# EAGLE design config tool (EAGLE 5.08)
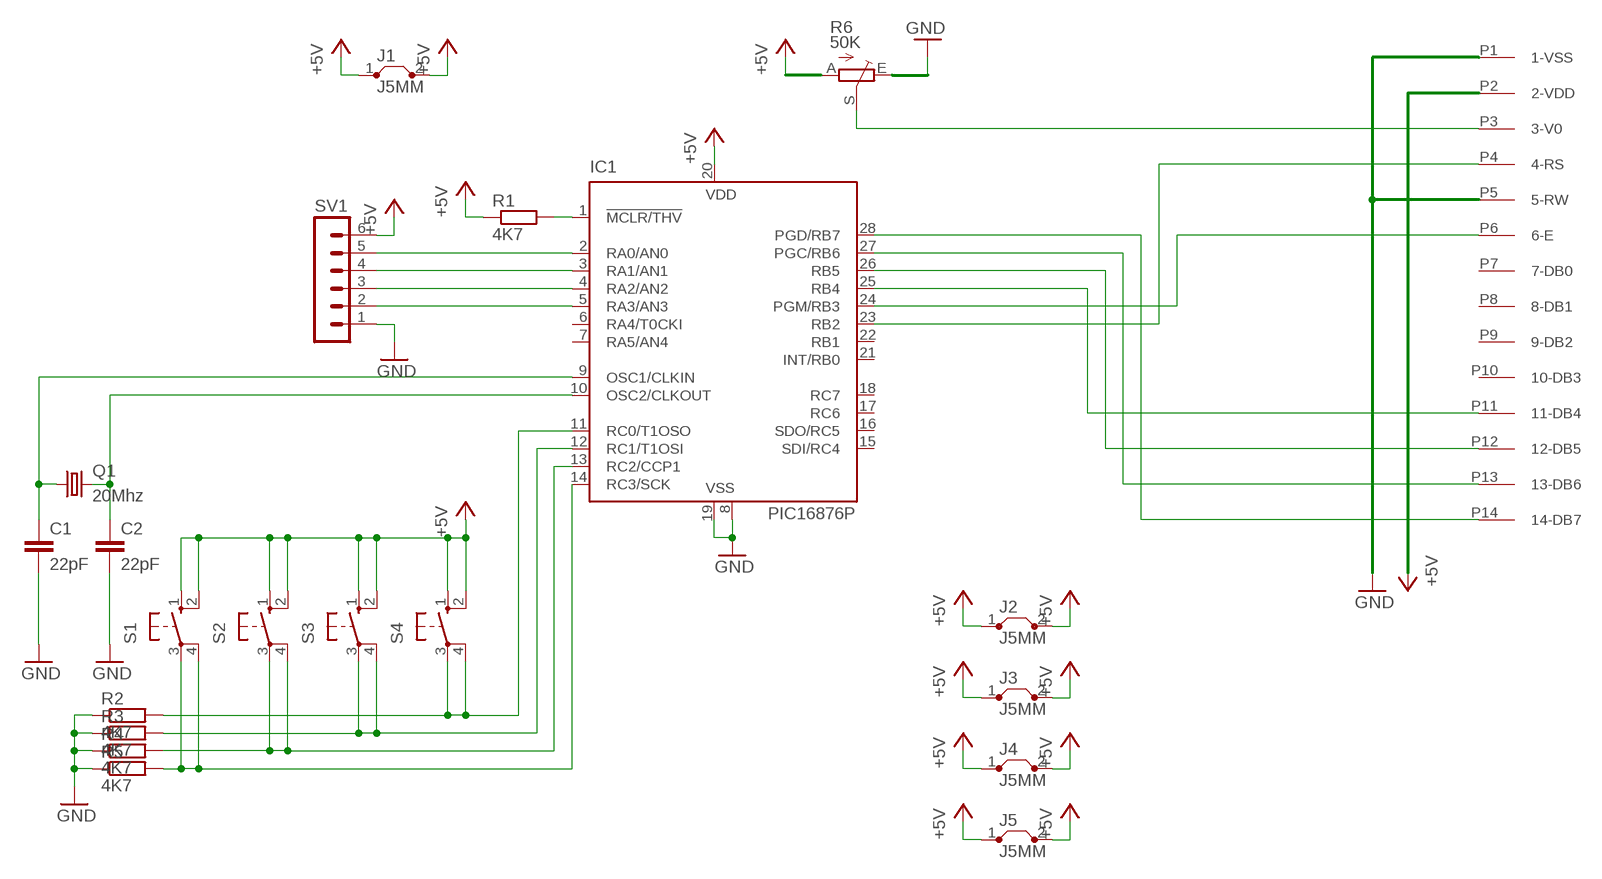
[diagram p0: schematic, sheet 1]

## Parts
C1  22pF  C-EU025-025X050  [C025-025X050]
C2  22pF  C-EU025-025X050  [C025-025X050]
IC1  PIC16876P  [DIL28-3]
J1  J5MM  [05]
J2  J5MM  [05]
J3  J5MM  [05]
J4  J5MM  [05]
J5  J5MM  [05]
Q1  20Mhz  CRYSTALHC18U-V  [HC18U-V]
R1  4K7  R-EU_0207/7  [0207/7]
R2  4K7  R-EU_0207/12  [0207/12]
R3  4K7  R-EU_0207/12  [0207/12]
R4  4K7  R-EU_0207/12  [0207/12]
R5  4K7  R-EU_0207/12  [0207/12]
R6  50K  TRIM_EU-B25P  [B25P]
S1  10-XX  [B3F-10XX]
S2  10-XX  [B3F-10XX]
S3  10-XX  [B3F-10XX]
S4  10-XX  [B3F-10XX]
SV1  MA06-1  [MA06-1]
U$1  16X2LCD  [NO_BACKLIGHT]

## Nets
+5V: IC1.20(VDD) J1.1 J1.2 J2.1 J2.2 J3.1 J3.2 J4.1 J4.2 J5.1 J5.2 R1.1 R6.A S1.1(S) S1.2(S1) S2.1(S) S2.2(S1) S3.1(S) S3.2(S1) S4.1(S) S4.2(S1) SV1.6 U$1.P2(2-VDD)
GND: C1.2 C2.2 IC1.8(VSS) IC1.19(VSS) R2.1 R3.1 R4.1 R5.1 R6.E SV1.1 U$1.P1(1-VSS) U$1.P5(5-RW)
N$1: IC1.28(PGD/RB7) U$1.P14(14-DB7)
N$2: IC1.27(PGC/RB6) U$1.P13(13-DB6)
N$3: IC1.26(RB5) U$1.P12(12-DB5)
N$4: IC1.25(RB4) U$1.P11(11-DB4)
N$5: IC1.23(RB2) U$1.P4(4-RS)
N$6: IC1.24(PGM/RB3) U$1.P6(6-E)
N$7: R6.S U$1.P3(3-V0)
N$8: C2.1 IC1.10(OSC2/CLKOUT) Q1.2
N$9: IC1.2(RA0/AN0) SV1.5
N$10: IC1.3(RA1/AN1) SV1.4
N$11: IC1.4(RA2/AN2) SV1.3
N$12: IC1.5(RA3/AN3) SV1.2
N$13: C1.1 IC1.9(OSC1/CLKIN) Q1.1
N$14: IC1.1(!MCLR/THV) R1.2
N$15: IC1.11(RC0/T1OSO) R2.2 S4.3(P) S4.4(P1)
N$16: IC1.12(RC1/T1OSI) R3.2 S3.3(P) S3.4(P1)
N$17: IC1.13(RC2/CCP1) R4.2 S2.3(P) S2.4(P1)
N$18: IC1.14(RC3/SCK) R5.2 S1.3(P) S1.4(P1)
Unconnected: IC1.6(RA4/T0CKI) IC1.7(RA5/AN4) IC1.15(SDI/RC4) IC1.16(SDO/RC5) IC1.17(RC6) IC1.18(RC7) IC1.21(INT/RB0) IC1.22(RB1) U$1.P7(7-DB0) U$1.P8(8-DB1) U$1.P9(9-DB2) U$1.P10(10-DB3)

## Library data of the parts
C1 C2 = rcl:C-EU: CAPACITOR, European symbol
IC1 = microchip:PIC16*876: MICROCONTROLLER flash type
J1-J5 = jumper:J: Bridge
Q1 = crystal:CRYSTAL: CRYSTAL
R1-R5 = rcl:R-EU_: RESISTOR, European symbol
R6 = pot:TRIM_EU-: POTENTIOMETER
S1-S4 = switch-omron:10-XX: OMRON SWITCH
SV1 = con-lstb:MA06-1: PIN HEADER
U$1 = lcd_nobacklight:16X2LCD: 16x2 LCD - no backlight

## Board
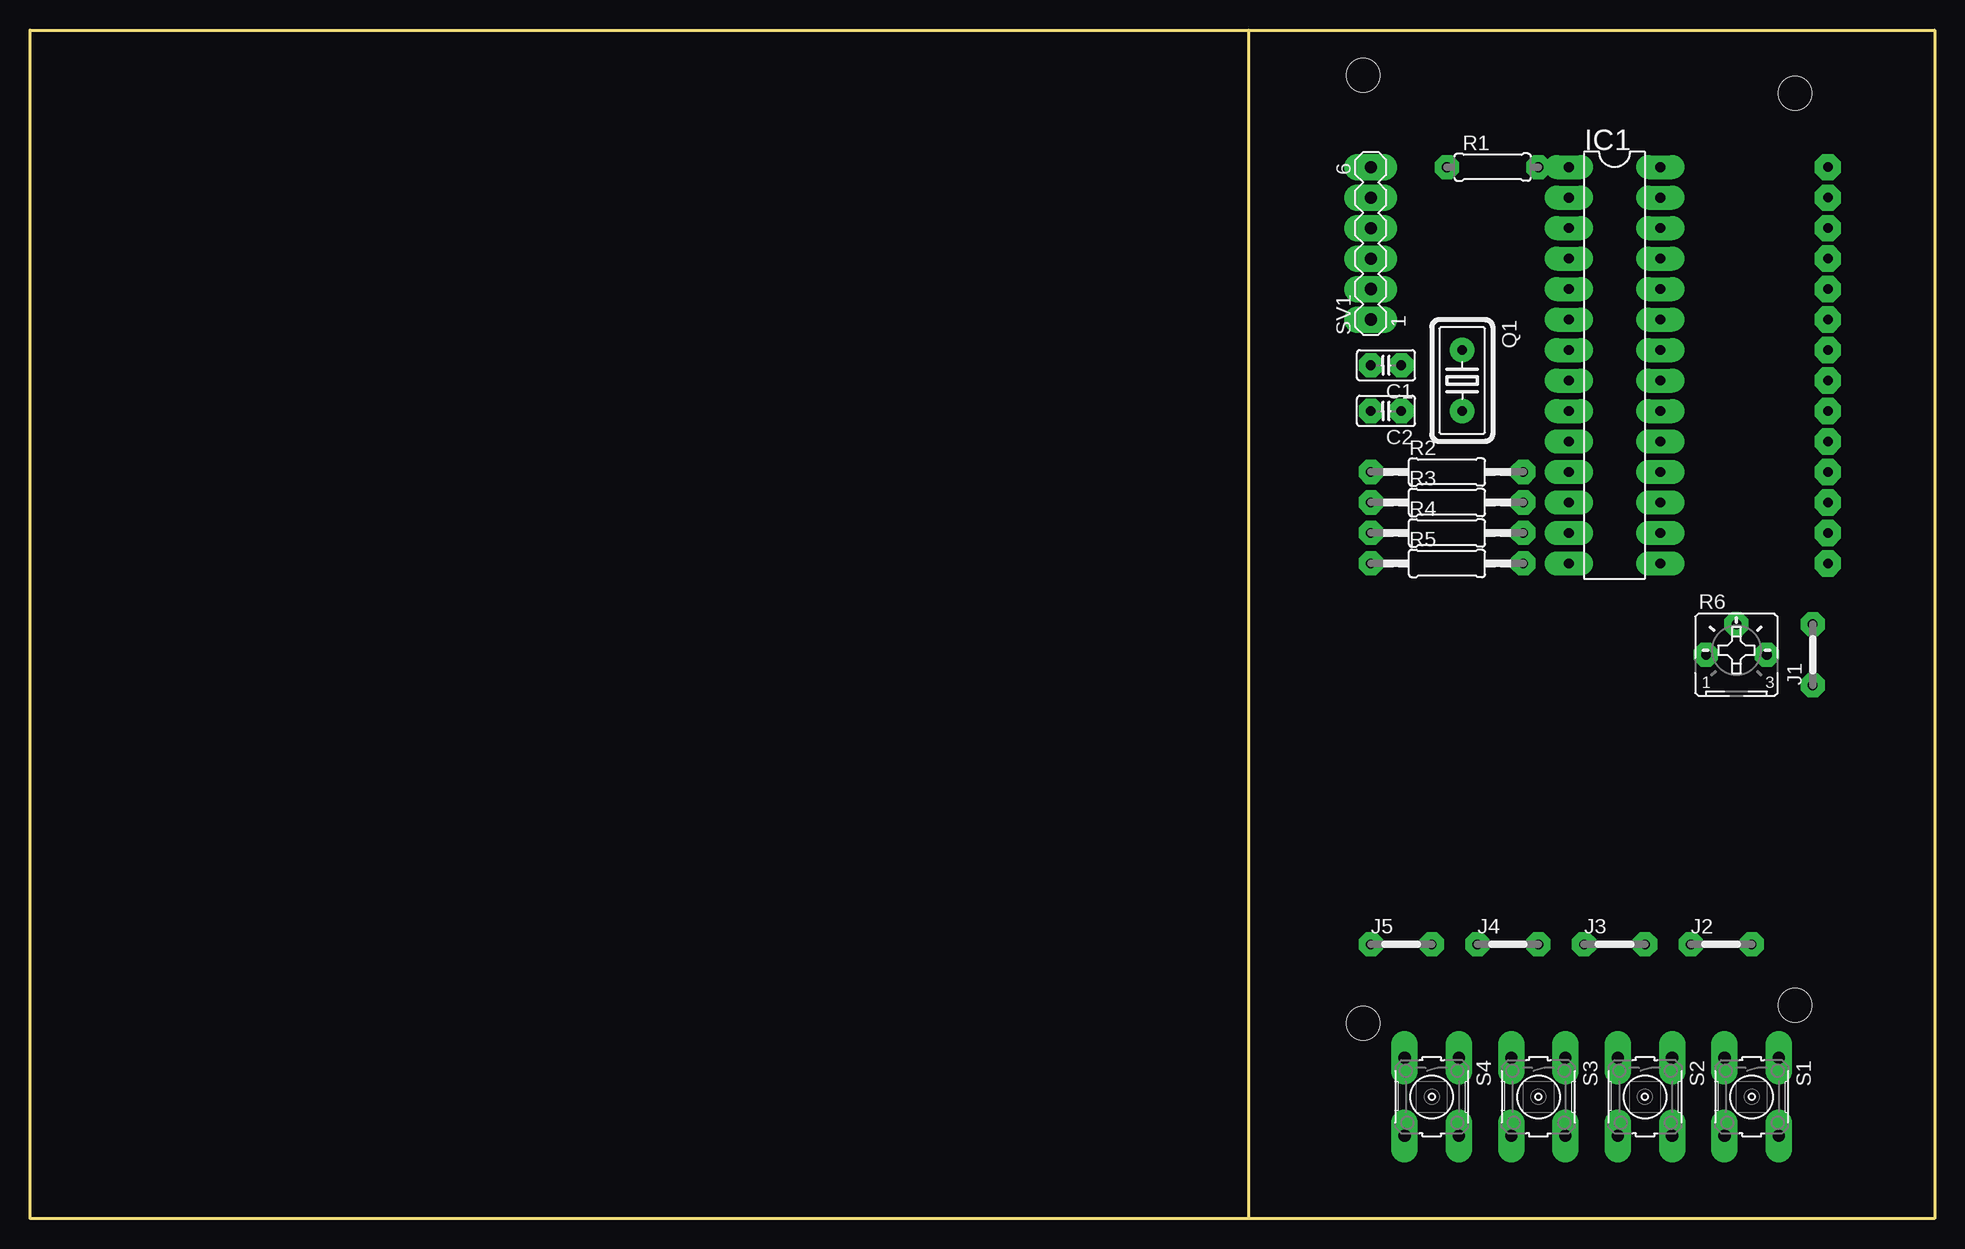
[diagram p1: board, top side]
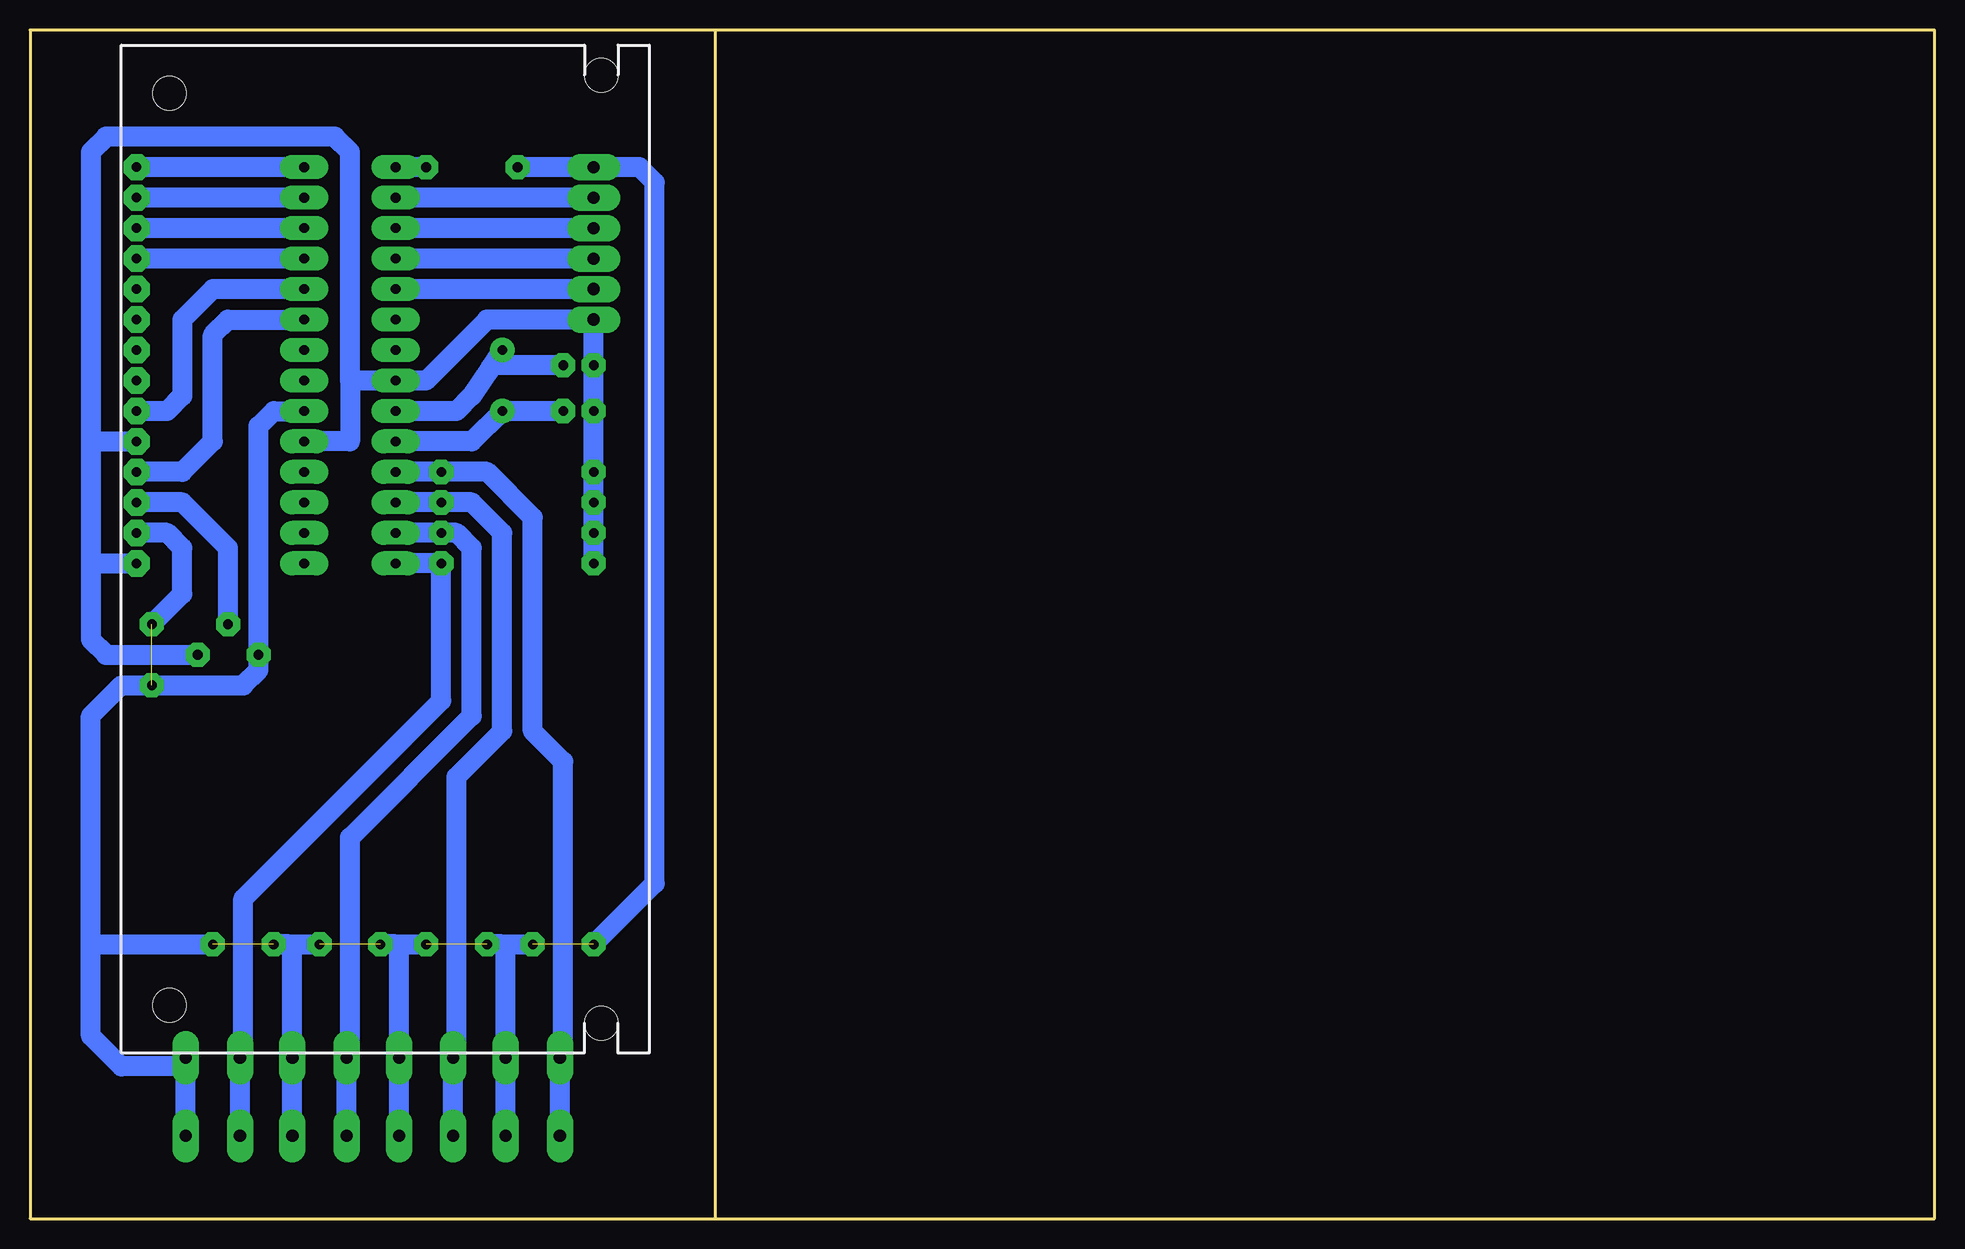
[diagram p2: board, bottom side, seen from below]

Size 158.75 x 99.06 mm. Coordinates in mm from the lower left corner, seen from the top.
Outline: 101.6,99.06 0,99.06 0,0 101.6,0
Outline: 101.6,99.06 158.75,99.06 158.75,0 101.6,0
Outline: 101.6,0 101.6,99.06
Copper layers (1*16): Top 1mm / dielectric 1.5mm / Bottom 1mm
Design rules "DRC settings middle": minimum track width 1.2mm, minimum drill 24mil, track to track 0.4mm, track to pad 0.4mm, pad to pad 0.4mm, via to via 0.4mm, smd to smd 8mil, copper to edge 0.5mm, drill to drill 0.5mm, minimum pad ring 0.6mm, minimum via ring 1mm, stop-mask expansion 4mil, vias tented up to drill 0mil, thermal gap 10mil

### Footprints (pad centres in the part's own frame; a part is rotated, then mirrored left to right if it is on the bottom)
C025-025X050 = drill 0.813 octagon: 1 -1.27,0; 2 1.27,0
DIL28-3 = drill 0.813 long: 1 -16.51,-3.81; 2 -13.97,-3.81; 3 -11.43,-3.81; 4 -8.89,-3.81; 5 -6.35,-3.81; 6 -3.81,-3.81; 7 -1.27,-3.81; 8 1.27,-3.81; 9 3.81,-3.81; 10 6.35,-3.81; 11 8.89,-3.81; 12 11.43,-3.81; 13 13.97,-3.81; 14 16.51,-3.81; 15 16.51,3.81; 16 13.97,3.81; 17 11.43,3.81; 18 8.89,3.81; 19 6.35,3.81; 20 3.81,3.81; 21 1.27,3.81; 22 -1.27,3.81; 23 -3.81,3.81; 24 -6.35,3.81; 25 -8.89,3.81; 26 -11.43,3.81; 27 -13.97,3.81; 28 -16.51,3.81
05 = drill 0.813 pad 1.6 octagon: 1 -2.54,0; 2 2.54,0
HC18U-V = drill 0.813 round: 1 -2.54,0; 2 2.54,0
0207/7 = drill 0.813 octagon: 1 -3.81,0; 2 3.81,0
0207/12 = drill 0.813 octagon: 1 -6.35,0; 2 6.35,0
B25P = drill 0.813 octagon: A -2.54,0; E 2.54,0; S 0,2.54
B3F-10XX = drill 1.016 long: 1 -3.251,2.261; 2 3.251,2.261; 3 -3.251,-2.261; 4 3.251,-2.261
MA06-1 = drill 1.016 long: 1 -6.35,0; 2 -3.81,0; 3 -1.27,0; 4 1.27,0; 5 3.81,0; 6 6.35,0
NO_BACKLIGHT = drill 0.8 pad 2.184 octagon: P1 43.18,1.27; P2 40.64,1.27; P3 38.1,1.27; P4 35.56,1.27; P5 33.02,1.27; P6 30.48,1.27; P7 27.94,1.27; P8 25.4,1.27; P9 22.86,1.27; P10 20.32,1.27; P11 17.78,1.27; P12 15.24,1.27; P13 12.7,1.27; P14 10.16,1.27 | hole 2.8: 4,4; 80,4; 2.5,40; 81.5,40

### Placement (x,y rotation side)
C1  113.03,71.12 180 top
C2  113.03,67.31 180 top
IC1  132.08,71.12 270 top
J1  148.59,46.99 90 top
J2  140.97,22.86 0 top
J3  132.08,22.86 0 top
J4  123.19,22.86 0 top
J5  114.3,22.86 0 top
Q1  119.38,69.85 270 top
R1  121.92,87.63 0 top
R2  118.11,62.23 0 top
R3  118.11,59.69 0 top
R4  118.11,57.15 0 top
R5  118.11,54.61 0 top
R6  142.24,46.99 0 top
S1  143.51,10.16 270 top
S2  134.62,10.16 270 top
S3  125.73,10.16 270 top
S4  116.84,10.16 270 top
SV1  111.76,81.28 90 top
U$1  151.13,97.79 270 bottom

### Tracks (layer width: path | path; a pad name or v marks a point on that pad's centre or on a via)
+5V  (5 unrouted)
  Bottom 1.676: S4.2 S4.1 119.1,22.58 119.38,22.86 | S3.2 S3.1 127.99,22.58 128.27,22.86 | S1.2 S1.1 146.33,12.7 151.13,12.7 153.67,15.24 153.67,22.86 | S2.2 S2.1 136.88,22.58 137.16,22.86 J2.1 J3.2 | R1.1 SV1.6 107.95,87.63 106.68,86.36 106.68,27.94 J5.1 | IC1.20 138.43,67.31 139.7,66.04 R6.A 139.7,45.72 140.97,44.45 J1.1 151.13,44.45 153.67,41.91 153.67,22.86 | U$1.P2 147.32,57.15 146.05,55.88 146.05,52.07 J1.2 | 153.67,22.86 J2.2 | 128.27,22.86 J4.2 | 128.27,22.86 J3.1 | 119.38,22.86 J5.2 | 119.38,22.86 J4.1
GND
  Bottom 1.676: 132.08,69.85 IC1.8 125.73,69.85 120.65,74.93 SV1.1 C1.2 C2.2 R2.1 R3.1 R4.1 R5.1 | IC1.19 132.08,64.77 132.08,69.85 | 132.08,69.85 132.08,88.9 133.35,90.17 152.4,90.17 153.67,88.9 153.67,64.77 | 153.67,64.77 U$1.P5 | R6.E 152.4,46.99 153.67,48.26 153.67,54.61 | 153.67,64.77 153.67,54.61 | 153.67,54.61 U$1.P1
N$1
  Bottom 1.676: IC1.28 U$1.P14
N$2
  Bottom 1.676: IC1.27 U$1.P13
N$3
  Bottom 1.676: IC1.26 U$1.P12
N$4
  Bottom 1.676: IC1.25 U$1.P11
N$5
  Bottom 1.676: U$1.P4 146.05,62.23 143.51,64.77 143.51,73.66 142.24,74.93 IC1.23
N$6
  Bottom 1.676: U$1.P6 147.32,67.31 146.05,68.58 146.05,74.93 143.51,77.47 IC1.24
N$7
  Bottom 1.676: U$1.P3 146.05,59.69 142.24,55.88 R6.S
N$8
  Bottom 1.676: IC1.10 121.92,64.77 Q1.2 C2.1
N$9
  Bottom 1.676: SV1.5 IC1.2
N$10
  Bottom 1.676: SV1.4 IC1.3
N$11
  Bottom 1.676: SV1.3 IC1.4
N$12
  Bottom 1.676: SV1.2 IC1.5
N$13
  Bottom 1.676: IC1.9 123.19,67.31 121.92,68.58 120.36,70.92 | 120.36,70.92 Q1.1 | C1.1 120.16,71.12 120.36,70.92
N$14
  Bottom 1.676: R1.2 IC1.1
N$15
  Bottom 1.676: IC1.11 R2.2 120.65,62.23 116.84,58.42 116.84,40.64 114.3,38.1 114.3,13.69 S4.3 S4.4
N$16
  Bottom 1.676: IC1.12 R3.2 121.92,59.69 119.38,57.15 119.38,40.64 123.19,36.83 123.19,13.69 S3.3 S3.4
N$17
  Bottom 1.676: IC1.13 R4.2 123.19,57.15 121.92,55.88 121.92,41.91 132.08,31.75 132.08,13.69 S2.3 S2.4
N$18
  Bottom 1.676: IC1.14 R5.2 124.46,43.18 140.97,26.67 140.97,13.69 S1.3 S1.4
